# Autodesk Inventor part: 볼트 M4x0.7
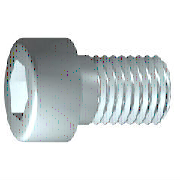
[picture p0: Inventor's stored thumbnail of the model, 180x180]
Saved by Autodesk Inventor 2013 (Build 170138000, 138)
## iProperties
IsCustomPart: 1
Created: 2015-10
Part Number: 볼트 M4x0.7
Material: 스테인리스강
Description: 6각머리 태핑 나사
Document SubType Name: Modeling
Standard: KS B 1003
Designer: mdu
Standards Organization: KS
Language: ko-KR
Size Designation: M 4 x 16
Categories: <MemberInstance><Categories><Category DisplayName="조임쇠" InternalName="e4da775c-781d-43d5-af7c-5136215cf5a6" Mnemonic="FSTN"><Category DisplayName="볼트" InternalN
Density: 8.08 g/cm^3
Mass: 2.70334 g
Surface Area: 3.81118 cm^2
Volume: 0.334572 cm^3
Author: mdu
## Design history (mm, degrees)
sketch "스케치1"
  geometry: L1 (-1, 0)-(16, 0); L2 (16, 0)-(16, 2); L3 (16, 2)-(1.75, 2); L4 (1.75, 2)-(1.32, 2); L5 (1.32, 2)-(0, 2); L6 (0, 2)-(0, 3.5); L7 (0, 3.5)-(-4, 3.5); L8 (-4, 3.5)-(-4, 1.732); L9 (-4, 1.732)-(-2, 1.732); L10 (-2, 1.732)-(-1, 0); L11 (-8, 0)-(20, 0) reference; L12 (0, -0.7)-(0, 4.2) reference; L13 (1.75, 2)-(0, 2)
  constraints: 22 end point, 6 parallel, 2 collinear, 2 perpendicular, 1 horizontal, 1 point on line
  dimensions: "d1" = 14.25 distance from line of L3.end L2 (= GEL); "d2" = 0.42952 distance of L4.end L3.end (computed from GAL); "d3" = 4 distance between parallel lines of L8 L6 (= KOH); "d4" = 2 distance of L8.end L9.end (= INTI); "d5" = 60 deg angle of L10 L1; "d6" = 4 diameter of L3 L1 (= GD); "d7" = 4 diameter of L5 L1 (= BDM); "d8" = 3.4641 diameter of L9 L1 (= 1.1547 x SW); "d9" = 7 diameter of L7 L1 (= KOD); "d26" = 16 distance between parallel lines of L12 L2 (= NLG)
revolve "본체" sketch "스케치1" stored, may be unused: angle "d10" = 90 deg
sketch "스케치2"
  geometry: L1 (0, -4.9)-(0, 4.9) reference; L2 (-4.9, 0)-(4.9, 0) reference; L3 (1.732, 0)-(0.866, -1.5); L4 (0.866, -1.5)-(-0.866, -1.5); L5 (-0.866, -1.5)-(-1.732, 0); L6 (-1.732, 0)-(-0.866, 1.5); L7 (-0.866, 1.5)-(0.866, 1.5); L8 (0.866, 1.5)-(1.732, 0); 2 further points
  constraints: 12 end point, 1 coincident, 1 horizontal alignment, 1 point on line, 12 other
extrude "슬롯" join sketch "스케치2" stored distance "d11" = 10; taper "d12" = 0 deg
workplane "Work Plane1"
fillet "Fillet2" dims "d30" = 0.1 (= R)
body "Solid1"
fillet "모깎기1" dims "d17" = 0.4 (= RR)
feature "스레드" dims "d13" = 14.25 (= GEL), "d14" = 0
chamfer "모따기1" distance "d15" = 0.42941 (= -0.5 x SPD + 0.5 x GD); stored, may be unused: second distance "d16" = 0.42941 (= GUL), angle "d27" = 45 deg
other parameters: "GD" = 4 (= NND) [user parameter; used in 2 equation terms], "NLG" = 16 [user parameter; used in 1 equation term], "GEL" = 14.25 [user parameter; used in 2 equation terms], "KOD" = 7 [user parameter; used in 1 equation term], "KOH" = 4 [user parameter; used in 1 equation term], "INTI" = 2 [user parameter; used in 1 equation term], "GAL" = 0.42941 (= 0.61345 x PTC) [user parameter; used in 1 equation term], "GUL" = 0.42941 (= 0.61345 x PTC) [user parameter; used in 1 equation term], "BDM" = 4 (= NND) [user parameter; used in 1 equation term], "SW" = 3 [user parameter; used in 2 equation terms], "RR" = 0.4 [user parameter; used in 1 equation term], "SPD" = 3.14117 (= NND - 1.2269 x PTC) [user parameter; used in 1 equation term], "d19" = 0, "d28" = 0, "d29" = 0, "R" = 0.1 [user parameter; used in 1 equation term], "PHH" = 0.2 [user parameter], "GD1" = 3.14117 (= THREADDIA - 1.2269 x PTC) [user parameter], "THREADDIA" = 4 [user parameter; used in 1 equation term], "FAWI" = 45 deg [user parameter], "TPU" = 14.28571 (computed from PTC) [user parameter], "PTC" = 0.7 [user parameter; used in 5 equation terms], "NND" = 4 [user parameter; used in 3 equation terms], "TOA" = 30 deg [user parameter], "E0" = 3.465 (= 1.155 x SW) [user parameter]
